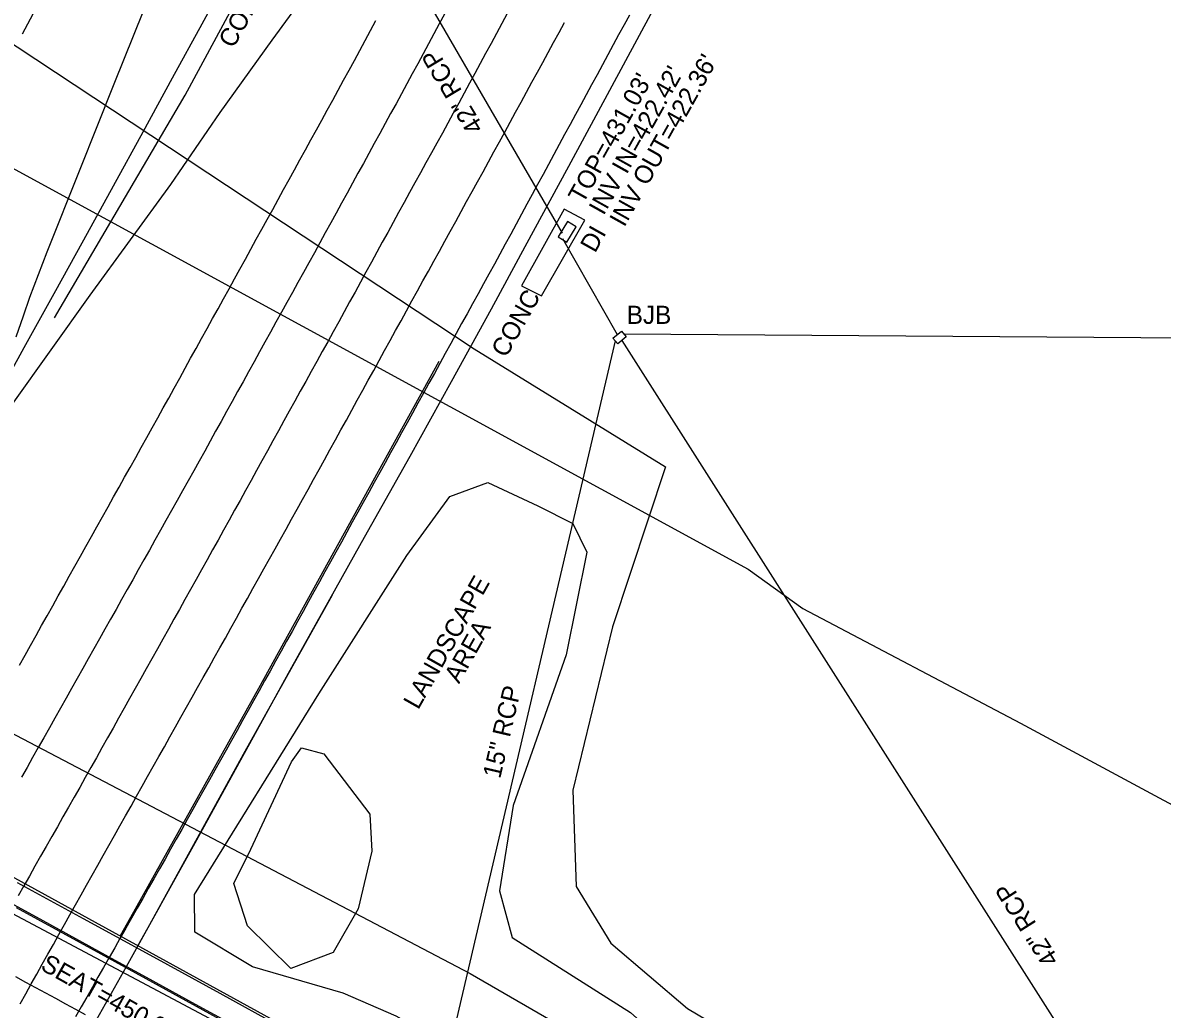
# Model space of a CAD drawing. Extents: x 2074109 to 2077820, y 741079 to 746031.
# Drawn here: x 2075614.7 to 2075865.9, y 743352.5 to 743570.1 of the extents above; entities that cross this region are included whole.
import ezdxf

# ---------------------------------------------------------------- set-up
doc = ezdxf.new("R2010")
doc.units = 0
for name, color, linetype in [('Exist Guardrail Cable Guide Rail', 7, 'Continuous'), ('Exist Horizontal Alignment', 7, 'Continuous'), ('Exist Roads EOP', 7, 'Continuous'), ('Exist Roads EOP Other', 7, 'Continuous'), ('Exist Roads EOT', 7, 'Continuous'), ('Exist Structure Major Bridge Seat Top Elevation', 7, 'Continuous'), ('Exist Structure Major Deck Tunnel Box Culvert', 7, 'Continuous'), ('Exist Structure Minor Drop Inlet', 7, 'Continuous'), ('Exist Structure Minor Drop Inlet Text', 7, 'Continuous'), ('Exist Structure Minor Drop Inlet Top Elevation', 7, 'Continuous'), ('Exist Structure Minor Junction Box', 7, 'Continuous'), ('Exist Structure Minor Junction Box Text', 7, 'Continuous'), ('Exist Structure Minor Paved Ditch or Gutter', 7, 'Continuous'), ('Exist Structure Minor Paved Ditch or Gutter Text', 7, 'Continuous'), ('Exist Structure Minor Pipes RCP 15 Inch', 7, 'Continuous'), ('Exist Structure Minor Pipes RCP 15 Inch Text', 7, 'Continuous'), ('Exist Structure Minor Pipes RCP 18 Inch', 7, 'Continuous'), ('Exist Structure Minor Pipes RCP 42 Inch', 7, 'Continuous'), ('Exist Structure Minor Pipes RCP 42 Inch Invert', 7, 'Continuous'), ('Exist Structure Minor Pipes RCP 42 Inch Text', 7, 'Continuous'), ('Exist Utilities Gas UG Line SUE LOS B', 7, 'Continuous'), ('Exist Utilities Power UG Cable SUE LOS B', 7, 'Continuous'), ('Exist Utilities Telephone UG Conduit SUE LOS B', 7, 'Continuous'), ('Exist Utilities Water UG Line SUE LOS B', 7, 'Continuous'), ('Exist Vegetation Hedge Row', 7, 'Continuous'), ('Exist Vegetation Hedge Row Text', 7, 'Continuous'), ('Exist Vegetation Woods Line', 7, 'Continuous')]:
    doc.layers.add(name, color=color, linetype=linetype)

msp = doc.modelspace()

# ---------------------------------------------------------------- linework, layer by layer
at = {"layer": 'Exist Guardrail Cable Guide Rail'}
msp.add_line((2075621.69, 743504.99), (2075650.49, 743554.11), dxfattribs=at)
msp.add_lwpolyline([(2075650.49, 743554.11), (2075673.2, 743596.24), (2075687.81, 743623.41), (2075710.4, 743665.84), (2075732.48, 743708.32), (2075762.33, 743765.12), (2075783.84, 743808.03), (2075814.02, 743866.81), (2075836.08, 743909.75), (2075849.04, 743935.68), (2075864.46, 743966.93), (2075885.81, 744010.38), (2075906.82, 744052.95), (2075934.19, 744109.59), (2075948.31, 744139.02)], dxfattribs=at)
at = {"layer": 'Exist Horizontal Alignment'}
msp.add_arc((2065746.77, 748969.72), 11283.45, 330.581241, 339.398504, dxfattribs=at)
at = {"layer": 'Exist Roads EOP'}
for points in [[(2075681.89, 743583.08), (2075669.6, 743566.23), (2075658.12, 743550.34), (2075647.24, 743534.4), (2075629.48, 743509.98), (2075612.24, 743485.93)], [(2075753.6, 743572.88), (2075735, 743538.43), (2075725.37, 743520.68), (2075717.94, 743506.9), (2075709.15, 743490.9), (2075700.01, 743474.45), (2075689.28, 743455.36), (2075673.57, 743427.2), (2075652.59, 743389.13), (2075637.45, 743361.85), (2075623.56, 743337.14), (2075608.64, 743310.49)], [(2075613.21, 743500.83), (2075614.86, 743505.48), (2075616.24, 743509.55), (2075620.07, 743519.56), (2075627.3, 743537.82), (2075634.82, 743556.62), (2075641.39, 743572.86)], [(2075640.04, 743366.53), (2075642.3, 743370.52), (2075663.34, 743408.74), (2075682.99, 743443.91)]]:
    msp.add_lwpolyline(points, dxfattribs=at)
at = {"layer": 'Exist Roads EOP Other'}
msp.add_lwpolyline([(2075613.42, 743380.47), (2075627.96, 743372.52), (2075643.51, 743364.05), (2075658.13, 743356.03), (2075671.42, 743348.72), (2075673.57, 743347.48), (2075672.26, 743342.96), (2075668.5, 743344.94), (2075661.17, 743349), (2075652.74, 743353.59), (2075641.93, 743359.53), (2075635.06, 743363.28), (2075619.2, 743371.98), (2075608.74, 743377.69)], dxfattribs=at)
at = {"layer": 'Exist Roads EOT'}
for points in [[(2075721.5, 743572.13), (2075720.31, 743569.93), (2075719.12, 743567.73), (2075717.93, 743565.53), (2075716.74, 743563.33), (2075715.56, 743561.13), (2075714.37, 743558.94), (2075713.18, 743556.74), (2075711.99, 743554.54), (2075710.8, 743552.34), (2075709.61, 743550.14), (2075708.41, 743547.95), (2075707.2, 743545.76), (2075705.99, 743543.57), (2075704.78, 743541.39), (2075703.57, 743539.2), (2075702.37, 743537.01), (2075701.16, 743534.82), (2075699.96, 743532.63), (2075698.76, 743530.43), (2075697.55, 743528.24), (2075696.35, 743526.05), (2075695.15, 743523.86), (2075693.95, 743521.67), (2075692.74, 743519.48), (2075691.54, 743517.29), (2075690.34, 743515.1), (2075689.14, 743512.9), (2075687.94, 743510.71), (2075686.75, 743508.51), (2075685.55, 743506.31), (2075684.35, 743504.13), (2075683.14, 743501.94), (2075681.93, 743499.75), (2075680.71, 743497.57), (2075679.5, 743495.38), (2075678.29, 743493.19), (2075677.08, 743491), (2075675.87, 743488.82), (2075674.66, 743486.63), (2075673.45, 743484.44), (2075672.24, 743482.26), (2075671.03, 743480.07), (2075669.82, 743477.88), (2075668.61, 743475.69), (2075667.41, 743473.5), (2075666.21, 743471.31), (2075665.02, 743469.11), (2075663.8, 743466.93), (2075662.59, 743464.74), (2075661.37, 743462.56), (2075660.16, 743460.37), (2075658.94, 743458.19), (2075657.73, 743456), (2075656.51, 743453.82), (2075655.3, 743451.63), (2075654.08, 743449.45), (2075652.87, 743447.27), (2075651.65, 743445.08), (2075650.43, 743442.9), (2075649.22, 743440.71), (2075648.01, 743438.53), (2075646.79, 743436.34), (2075645.58, 743434.16), (2075644.35, 743431.98), (2075643.13, 743429.8), (2075641.91, 743427.62), (2075640.69, 743425.44), (2075639.46, 743423.26), (2075638.24, 743421.08), (2075637.02, 743418.89), (2075635.8, 743416.71), (2075634.57, 743414.53), (2075633.35, 743412.35), (2075632.13, 743410.17), (2075630.91, 743407.99), (2075629.68, 743405.81), (2075628.46, 743403.63), (2075627.24, 743401.45), (2075626.02, 743399.27), (2075624.78, 743397.1), (2075623.54, 743394.93), (2075622.31, 743392.75), (2075621.07, 743390.58), (2075619.83, 743388.41), (2075618.6, 743386.24), (2075617.36, 743384.07), (2075616.12, 743381.89), (2075614.89, 743379.72), (2075613.65, 743377.55)], [(2075613.96, 743428.4), (2075615.17, 743430.59), (2075616.39, 743432.77), (2075617.61, 743434.95), (2075618.83, 743437.13), (2075620.05, 743439.32), (2075621.27, 743441.5), (2075622.49, 743443.68), (2075623.71, 743445.86), (2075624.93, 743448.04), (2075626.15, 743450.23), (2075627.37, 743452.41), (2075628.59, 743454.59), (2075629.81, 743456.77), (2075631.03, 743458.95), (2075632.25, 743461.14), (2075633.47, 743463.32), (2075634.69, 743465.5), (2075635.91, 743467.68), (2075637.13, 743469.86), (2075638.35, 743472.04), (2075639.57, 743474.23), (2075640.79, 743476.41), (2075642.01, 743478.59), (2075643.23, 743480.77), (2075644.44, 743482.96), (2075645.65, 743485.15), (2075646.86, 743487.33), (2075648.07, 743489.52), (2075649.28, 743491.71), (2075650.48, 743493.9), (2075651.69, 743496.09), (2075652.9, 743498.27), (2075654.11, 743500.46), (2075655.32, 743502.65), (2075656.53, 743504.84), (2075657.74, 743507.03), (2075658.95, 743509.21), (2075660.15, 743511.4), (2075661.36, 743513.59), (2075662.57, 743515.78), (2075663.77, 743517.97), (2075664.97, 743520.16), (2075666.17, 743522.36), (2075667.38, 743524.55), (2075668.58, 743526.74), (2075669.78, 743528.93), (2075670.99, 743531.12), (2075672.19, 743533.31), (2075673.39, 743535.5), (2075674.59, 743537.69), (2075675.8, 743539.89), (2075677, 743542.08), (2075678.2, 743544.27), (2075679.41, 743546.46), (2075680.61, 743548.65), (2075681.81, 743550.84), (2075683.01, 743553.03), (2075684.22, 743555.22), (2075685.42, 743557.42), (2075686.61, 743559.62), (2075687.8, 743561.81), (2075688.99, 743564.01), (2075690.18, 743566.21), (2075691.37, 743568.41), (2075692.56, 743570.6)], [(2075707.7, 743572.03), (2075706.51, 743569.84), (2075705.32, 743567.64), (2075704.13, 743565.44), (2075702.94, 743563.24), (2075701.76, 743561.04), (2075700.57, 743558.84), (2075699.38, 743556.64), (2075698.19, 743554.44), (2075696.99, 743552.25), (2075695.79, 743550.05), (2075694.6, 743547.86), (2075693.4, 743545.67), (2075692.19, 743543.47), (2075690.99, 743541.28), (2075689.79, 743539.09), (2075688.59, 743536.9), (2075687.39, 743534.71), (2075686.19, 743532.52), (2075684.98, 743530.32), (2075683.78, 743528.13), (2075682.58, 743525.94), (2075681.38, 743523.75), (2075680.18, 743521.56), (2075678.97, 743519.37), (2075677.76, 743517.18), (2075676.55, 743514.99), (2075675.34, 743512.8), (2075674.13, 743510.62), (2075672.92, 743508.43), (2075671.71, 743506.24), (2075670.5, 743504.05), (2075669.29, 743501.87), (2075668.08, 743499.68), (2075666.87, 743497.49), (2075665.66, 743495.31), (2075664.45, 743493.12), (2075663.24, 743490.93), (2075662.03, 743488.74), (2075660.82, 743486.56), (2075659.61, 743484.37), (2075658.41, 743482.18), (2075657.2, 743479.99), (2075656, 743477.79), (2075654.8, 743475.6), (2075653.59, 743473.42), (2075652.36, 743471.24), (2075651.14, 743469.06), (2075649.92, 743466.88), (2075648.69, 743464.7), (2075647.47, 743462.52), (2075646.25, 743460.34), (2075645.03, 743458.16), (2075643.8, 743455.98), (2075642.58, 743453.8), (2075641.36, 743451.61), (2075640.14, 743449.43), (2075638.92, 743447.25), (2075637.69, 743445.07), (2075636.47, 743442.89), (2075635.25, 743440.71), (2075634.03, 743438.53), (2075632.8, 743436.35), (2075631.57, 743434.18), (2075630.35, 743432), (2075629.12, 743429.82), (2075627.89, 743427.64), (2075626.66, 743425.46), (2075625.44, 743423.29), (2075624.21, 743421.11), (2075622.98, 743418.93), (2075621.75, 743416.75), (2075620.53, 743414.58), (2075619.3, 743412.4), (2075618.07, 743410.22), (2075616.85, 743408.04), (2075615.62, 743405.86), (2075614.4, 743403.68)], [(2075616.89, 743571.96), (2075615.7, 743569.76), (2075614.5, 743567.57)], [(2075748.46, 743571.81), (2075747.27, 743569.61), (2075746.07, 743567.41), (2075744.88, 743565.22), (2075743.69, 743563.02), (2075742.5, 743560.82), (2075741.31, 743558.63), (2075740.12, 743556.43), (2075738.92, 743554.23), (2075737.73, 743552.03), (2075736.54, 743549.84), (2075735.35, 743547.64), (2075734.16, 743545.44), (2075732.97, 743543.24), (2075731.78, 743541.04), (2075730.59, 743538.84), (2075729.4, 743536.65), (2075728.21, 743534.45), (2075727.03, 743532.25), (2075725.84, 743530.05), (2075724.65, 743527.85), (2075723.46, 743525.65), (2075722.27, 743523.45), (2075721.07, 743521.26), (2075719.87, 743519.07), (2075718.66, 743516.88), (2075717.46, 743514.68), (2075716.26, 743512.49), (2075715.06, 743510.3), (2075713.86, 743508.11), (2075712.66, 743505.92), (2075711.45, 743503.73), (2075710.25, 743501.53), (2075709.05, 743499.34), (2075707.85, 743497.15), (2075706.64, 743494.96), (2075705.44, 743492.77), (2075704.23, 743490.58), (2075703.02, 743488.39), (2075701.82, 743486.2), (2075700.61, 743484.01), (2075699.41, 743481.82), (2075698.2, 743479.63), (2075697, 743477.44), (2075695.79, 743475.25), (2075694.58, 743473.06), (2075693.38, 743470.88), (2075692.17, 743468.69), (2075690.96, 743466.5), (2075689.76, 743464.31), (2075688.55, 743462.12), (2075687.34, 743459.93), (2075686.14, 743457.74), (2075684.93, 743455.55), (2075683.72, 743453.36), (2075682.52, 743451.17), (2075681.31, 743448.98), (2075680.1, 743446.79), (2075678.89, 743444.61), (2075677.68, 743442.42), (2075676.47, 743440.23), (2075675.26, 743438.05), (2075674.05, 743435.86), (2075672.84, 743433.67), (2075671.62, 743431.49), (2075670.41, 743429.3), (2075669.2, 743427.11), (2075667.99, 743424.93), (2075666.78, 743422.74), (2075665.56, 743420.55), (2075664.35, 743418.37), (2075663.14, 743416.18), (2075661.93, 743414), (2075660.71, 743411.81), (2075659.49, 743409.63), (2075658.27, 743407.45), (2075657.05, 743405.27), (2075655.83, 743403.09), (2075654.61, 743400.91), (2075653.38, 743398.72), (2075652.16, 743396.54), (2075650.94, 743394.36), (2075649.72, 743392.18), (2075648.5, 743390), (2075647.27, 743387.82), (2075646.04, 743385.65), (2075644.81, 743383.47), (2075643.57, 743381.3), (2075642.34, 743379.12), (2075641.11, 743376.95), (2075639.88, 743374.77), (2075638.65, 743372.6), (2075637.41, 743370.42), (2075636.18, 743368.25), (2075634.95, 743366.07), (2075633.72, 743363.9), (2075632.48, 743361.72), (2075631.25, 743359.55), (2075630.02, 743357.37), (2075628.79, 743355.2), (2075627.56, 743353.02), (2075626.32, 743350.85)], [(2075614.08, 743353.73), (2075615.31, 743355.91), (2075616.53, 743358.1), (2075617.75, 743360.28), (2075618.97, 743362.46), (2075620.19, 743364.64), (2075621.41, 743366.82), (2075622.64, 743369), (2075623.86, 743371.18), (2075625.08, 743373.36), (2075626.31, 743375.54), (2075627.53, 743377.72), (2075628.75, 743379.9), (2075629.97, 743382.08), (2075631.2, 743384.26), (2075632.42, 743386.44), (2075633.64, 743388.62), (2075634.87, 743390.8), (2075636.09, 743392.98), (2075637.31, 743395.16), (2075638.54, 743397.34), (2075639.76, 743399.52), (2075640.99, 743401.7), (2075642.21, 743403.88), (2075643.44, 743406.06), (2075644.66, 743408.24), (2075645.89, 743410.42), (2075647.11, 743412.6), (2075648.33, 743414.77), (2075649.56, 743416.95), (2075650.78, 743419.13), (2075652.01, 743421.31), (2075653.23, 743423.49), (2075654.46, 743425.67), (2075655.68, 743427.85), (2075656.91, 743430.03), (2075658.13, 743432.21), (2075659.35, 743434.39), (2075660.57, 743436.57), (2075661.78, 743438.76), (2075663, 743440.94), (2075664.22, 743443.13), (2075665.43, 743445.31), (2075666.65, 743447.5), (2075667.86, 743449.68), (2075669.08, 743451.87), (2075670.29, 743454.05), (2075671.51, 743456.23), (2075672.72, 743458.42), (2075673.94, 743460.6), (2075675.16, 743462.79), (2075676.37, 743464.97), (2075677.59, 743467.16), (2075678.8, 743469.34), (2075680, 743471.53), (2075681.21, 743473.72), (2075682.41, 743475.91), (2075683.62, 743478.1), (2075684.83, 743480.29), (2075686.03, 743482.48), (2075687.24, 743484.67), (2075688.44, 743486.86), (2075689.65, 743489.05), (2075690.85, 743491.24), (2075692.06, 743493.43), (2075693.27, 743495.62), (2075694.47, 743497.81), (2075695.68, 743500), (2075696.88, 743502.19), (2075698.09, 743504.38), (2075699.3, 743506.57), (2075700.5, 743508.76), (2075701.71, 743510.95), (2075702.91, 743513.14), (2075704.12, 743515.33), (2075705.32, 743517.52), (2075706.53, 743519.71), (2075707.73, 743521.9), (2075708.94, 743524.09), (2075710.14, 743526.28), (2075711.35, 743528.47), (2075712.55, 743530.66), (2075713.76, 743532.85), (2075714.96, 743535.04), (2075716.17, 743537.23), (2075717.37, 743539.42), (2075718.57, 743541.61), (2075719.77, 743543.81), (2075720.96, 743546), (2075722.16, 743548.2), (2075723.36, 743550.39), (2075724.55, 743552.58), (2075725.75, 743554.78), (2075726.95, 743556.97), (2075728.14, 743559.17), (2075729.34, 743561.36), (2075730.54, 743563.56), (2075731.73, 743565.75), (2075732.93, 743567.95), (2075734.13, 743570.14)], [(2075706.45, 743495.37), (2075666.66, 743423.27), (2075638.4, 743372.72), (2075636.12, 743368.69)], [(2075613.08, 743359.72), (2075615.28, 743358.52), (2075617.47, 743357.32), (2075619.67, 743356.13), (2075621.86, 743354.93), (2075624.06, 743353.74), (2075626.26, 743352.55), (2075628.46, 743351.36)]]:
    msp.add_lwpolyline(points, dxfattribs=at)
at = {"layer": 'Exist Structure Major Deck Tunnel Box Culvert'}
msp.add_line((2075449.46, 743471.22), (2075674.49, 743347.61), dxfattribs=at)
msp.add_lwpolyline([(2075613.19, 743374.96), (2075627.29, 743367.22), (2075641.78, 743359.29), (2075661.76, 743348.35), (2075669.86, 743343.91), (2075672.4, 743342.55), (2075671.61, 743341.08), (2075667.43, 743333.41), (2075663.22, 743325.62), (2075663.16, 743325.51), (2075655.17, 743310.71), (2075654.55, 743309.54), (2075645.71, 743293.8), (2075640.94, 743285.06), (2075638.76, 743281.09), (2075638.26, 743280.18), (2075635.54, 743275.22), (2075635.26, 743274.73), (2075631.66, 743268.09), (2075628.36, 743261.94), (2075623.93, 743264.43), (2075607.03, 743273.66)], dxfattribs=at)
at = {"layer": 'Exist Structure Minor Drop Inlet'}
msp.add_lwpolyline([(2075734.79, 743526.23), (2075732.74, 743522.88), (2075734.63, 743521.72), (2075736.69, 743525.07)], close=True, dxfattribs=at)
at = {"layer": 'Exist Structure Minor Junction Box'}
msp.add_lwpolyline([(2075744.82, 743500.55), (2075746.68, 743502.08), (2075747.72, 743500.81), (2075745.87, 743499.28)], close=True, dxfattribs=at)
at = {"layer": 'Exist Structure Minor Paved Ditch or Gutter'}
msp.add_lwpolyline([(2075734.05, 743528.99), (2075724.63, 743512.04), (2075729.06, 743509.88), (2075738.61, 743526.54), (2075734.05, 743528.99)], dxfattribs=at)
at = {"layer": 'Exist Structure Minor Pipes RCP 15 Inch'}
msp.add_line((2075704.51, 743325.08), (2075745.34, 743499.91), dxfattribs=at)
at = {"layer": 'Exist Structure Minor Pipes RCP 18 Inch'}
msp.add_line((2075747.2, 743501.45), (2076008.33, 743499.7), dxfattribs=at)
at = {"layer": 'Exist Structure Minor Pipes RCP 42 Inch'}
for p, q in [((2075690.47, 743598.26), (2075733.58, 743523.67)), ((2075733.71, 743522.54), (2075745.75, 743501.31)), ((2075746.8, 743500.04), (2075924.44, 743220.97))]:
    msp.add_line(p, q, dxfattribs=at)
at = {"layer": 'Exist Utilities Gas UG Line SUE LOS B'}
msp.add_lwpolyline([(2075544.69, 743574.93), (2075774.64, 743449.58), (2075786.68, 743440.92), (2075834.72, 743415.6), (2075897.9, 743381.57), (2075936.93, 743360.69), (2075971.28, 743343.48), (2075996.08, 743328.1)], dxfattribs=at)
at = {"layer": 'Exist Utilities Power UG Cable SUE LOS B'}
msp.add_lwpolyline([(2075533.27, 743615.97), (2075567.2, 743595.41), (2075714.24, 743498.15), (2075756.41, 743472.15), (2075744.73, 743436.84), (2075735.98, 743400.81), (2075736.7, 743379.57), (2075744.38, 743367.05), (2075761.28, 743352.67), (2075771.54, 743346.58), (2075788.66, 743330.79), (2075794.6, 743320.93)], dxfattribs=at)
at = {"layer": 'Exist Utilities Telephone UG Conduit SUE LOS B'}
msp.add_lwpolyline([(2074852.23, 743796.93), (2074858.98, 743788.14), (2074871.16, 743780.09), (2074884.61, 743773.35), (2074910.14, 743759.3), (2074929.12, 743745.39), (2074958.42, 743728.87), (2074997.61, 743706.69), (2075052.29, 743677.02), (2075084.82, 743660.77), (2075107.9, 743645.87), (2075165.73, 743622.21), (2075198.81, 743604.97), (2075246.84, 743581.99), (2075289.9, 743561.06), (2075322.06, 743548.08), (2075339.73, 743539.52), (2075355.79, 743530.19), (2075360.13, 743528.64), (2075373.71, 743515.02), (2075393.05, 743495.87), (2075443.09, 743463.69), (2075672.89, 743341.39)], dxfattribs=at)
at = {"layer": 'Exist Utilities Water UG Line SUE LOS B'}
msp.add_lwpolyline([(2074661.41, 743894.07), (2074669.03, 743889.86), (2074695.78, 743877.33), (2074733.5, 743856.32), (2074766.19, 743837.03), (2074806.52, 743814.12), (2074828.36, 743801.4), (2074869.77, 743778.77), (2075138.71, 743653.82), (2075174.59, 743638.37), (2075261.38, 743603.22), (2075296.53, 743589.33), (2075345.56, 743568.62), (2075373.37, 743552.36), (2075399.34, 743536.02), (2075447.19, 743500.05), (2075713.36, 743360.43), (2075744.72, 743342.27), (2075764.85, 743330.17), (2075782.75, 743317.7), (2075822.78, 743289.56)], dxfattribs=at)
at = {"layer": 'Exist Vegetation Hedge Row'}
msp.add_lwpolyline([(2075739.04, 743453.34), (2075734.47, 743430.66), (2075722.82, 743397.44), (2075719.78, 743378.61), (2075722.57, 743368.36), (2075748.65, 743351.81), (2075768.88, 743333.68), (2075777.94, 743321.07), (2075779.48, 743315.18), (2075777.23, 743310.85), (2075770.98, 743308.92), (2075697.04, 743350.99), (2075685.33, 743356.04), (2075665.36, 743361.84), (2075652.63, 743369.54), (2075652.52, 743377.85), (2075679.93, 743422.09), (2075699.35, 743452.58), (2075708.86, 743465.58), (2075717.23, 743468.68), (2075728.23, 743463.53), (2075735.99, 743459.68), (2075739.04, 743453.34)], dxfattribs=at)
at = {"layer": 'Exist Vegetation Woods Line'}
msp.add_lwpolyline([(2075681.08, 743408.85), (2075691.19, 743395.51), (2075691.61, 743387.38), (2075688.61, 743374.63), (2075683.1, 743365.02), (2075673.79, 743361.47), (2075664.23, 743370.92), (2075661.19, 743380.27), (2075664.93, 743387.85), (2075673.94, 743407.09), (2075676.13, 743410.14), (2075681.08, 743408.85)], dxfattribs=at)

# ---------------------------------------------------------------- texts
at = {"layer": 'Exist Structure Major Bridge Seat Top Elevation'}
msp.add_text("SEAT=450.93'", height=4, rotation=330.742, dxfattribs=at).set_placement((2075618.34, 743361.37))
at = {"layer": 'Exist Structure Minor Drop Inlet Text'}
msp.add_text('DI', height=4, rotation=60.7411, dxfattribs=at).set_placement((2075740.87, 743519.15))
at = {"layer": 'Exist Structure Minor Drop Inlet Top Elevation'}
msp.add_text("TOP=431.03'", height=4, rotation=60.7411, dxfattribs=at).set_placement((2075738.21, 743529.99))
at = {"layer": 'Exist Structure Minor Junction Box Text'}
msp.add_text('BJB', height=4, dxfattribs=at).set_placement((2075747.86, 743503.68))
at = {"layer": 'Exist Structure Minor Paved Ditch or Gutter Text'}
for p in [(2075661.1, 743564.27), (2075721.25, 743496.02)]:
    msp.add_text('CONC', height=4, rotation=60.742, dxfattribs=at).set_placement(p)
at = {"layer": 'Exist Structure Minor Pipes RCP 15 Inch Text'}
msp.add_text('15" RCP', height=4, rotation=76.8554, dxfattribs=at).set_placement((2075719.94, 743403.23))
at = {"layer": 'Exist Structure Minor Pipes RCP 42 Inch Invert'}
for s, p in [("INV OUT=422.36'", (2075747.32, 743524.85)), ("INV IN=422.42'", (2075742.75, 743527.43))]:
    msp.add_text(s, height=4, rotation=60.7411, dxfattribs=at).set_placement(p)
at = {"layer": 'Exist Structure Minor Pipes RCP 42 Inch Text'}
for rotation, p in [(120.9733, (2075716.43, 743547.04)), (122.4789, (2075843.3, 743363.52))]:
    msp.add_text('42" RCP', height=4, rotation=rotation, dxfattribs=at).set_placement(p)
at = {"layer": 'Exist Vegetation Hedge Row Text'}
for s, p in [('LANDSCAPE ', (2075701.87, 743418.41)), ('AREA', (2075710.87, 743424.16))]:
    msp.add_text(s, height=4, rotation=60.5812, dxfattribs=at).set_placement(p)

doc.saveas('drawing.dxf')
